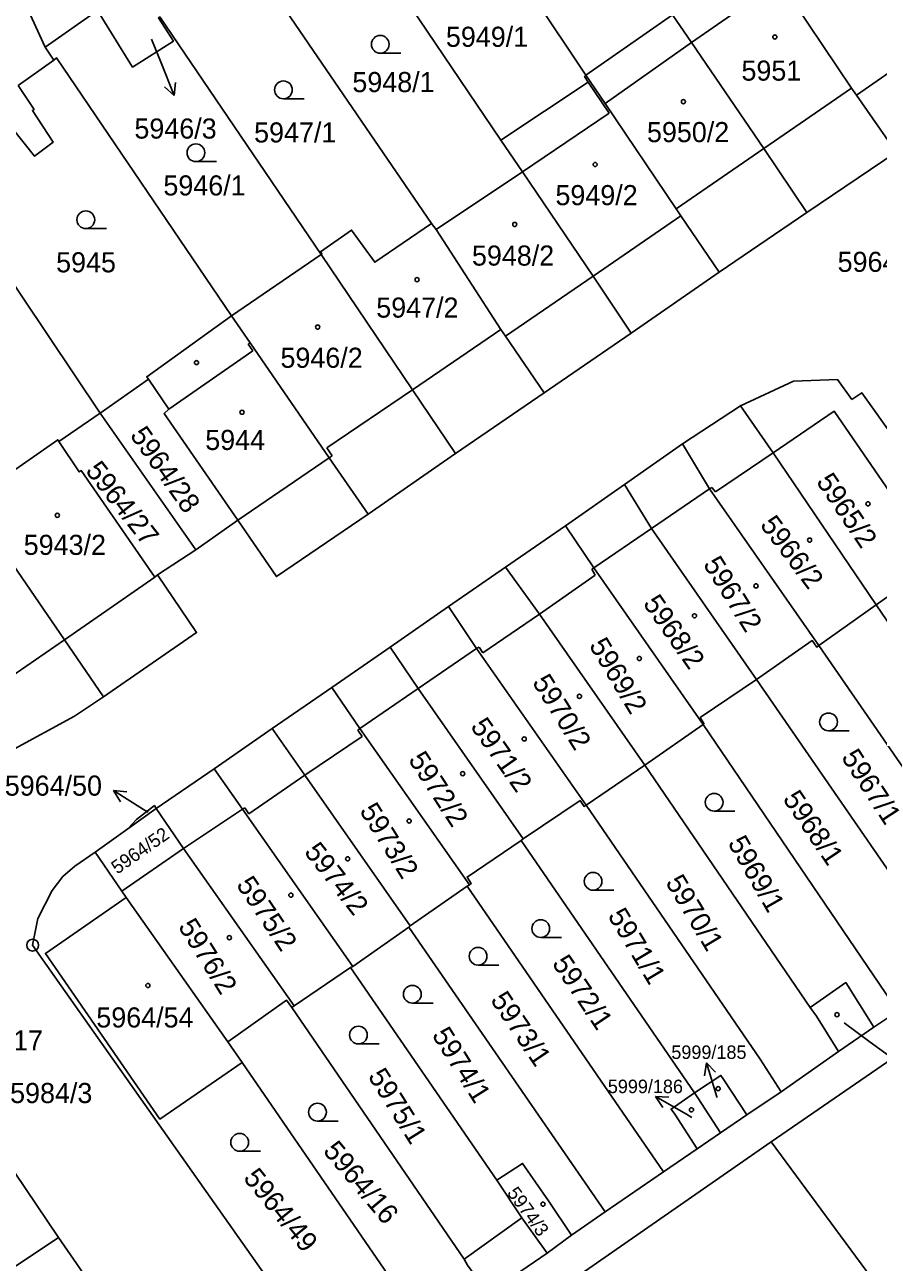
# Model space of a CAD drawing. Extents: x -644096 to -634268, y -1141430 to -1133463.
# Drawn here: x -639573 to -639500.8, y -1138928.4 to -1138823.8 of the extents above; entities that cross this region are included whole.
import ezdxf

# ---------------------------------------------------------------- set-up
doc = ezdxf.new("R2010")
doc.units = 0
for name, color, linetype in [('_CIVIL_CONSTRUCTION', 7, 'Continuous'), ('M_Svah_Nasyp', 7, 'Continuous'), ('M_Svah_Zarez', 7, 'Continuous'), ('svrsek_osa_sjezdy', 7, 'Continuous'), ('svrsek_osa_terminal_VRT', 7, 'Continuous'), ('svrsek_osa_VRT', 7, 'Continuous'), ('svrsek_popisy_VRT', 7, 'Continuous'), ('terminal_VRT', 7, 'Continuous')]:
    doc.layers.add(name, color=color, linetype=linetype)

msp = doc.modelspace()

# ---------------------------------------------------------------- linework, layer by layer
at = {"layer": '_CIVIL_CONSTRUCTION'}
for radius in [0.5, 0.0303]:
    msp.add_circle((-639572.35, -1138901.62), radius, dxfattribs=at)
at = {"layer": 'M_Svah_Nasyp'}
for p, q in [((-639509.18, -1138820.11), (-639516.63, -1138825.29)), ((-639502.69, -1138829.74), (-639494.75, -1138824.25)), ((-639523.93, -1138830.46), (-639516.63, -1138825.29)), ((-639523.6, -1138831.28), (-639525.36, -1138828.65)), ((-639510.51, -1138834.25), (-639503.1, -1138829.15)), ((-639530.93, -1138836.23), (-639523.6, -1138831.28)), ((-639510.51, -1138834.25), (-639517.92, -1138839.35)), ((-639517.53, -1138839.95), (-639524.94, -1138845.06)), ((-639524.94, -1138845.06), (-639532.37, -1138850.13)), ((-639532.76, -1138849.56), (-639540.24, -1138854.66)), ((-639560.84, -1138856.3), (-639553.74, -1138851.38)), ((-639554.12, -1138850.8), (-639553.96, -1138850.69)), ((-639553.74, -1138851.38), (-639554.12, -1138850.8)), ((-639547.46, -1138859.58), (-639540.24, -1138854.66)), ((-639547.01, -1138860.24), (-639547.46, -1138859.58)), ((-639547.26, -1138860.4), (-639555, -1138865.68)), ((-639547.26, -1138860.4), (-639547.01, -1138860.24)), ((-639509.74, -1138860), (-639514.6, -1138863.29)), ((-639514.92, -1138862.93), (-639515.11, -1138863.04)), ((-639514.6, -1138863.29), (-639514.92, -1138862.93)), ((-639520.02, -1138866.39), (-639515.11, -1138863.04)), ((-639524.89, -1138869.71), (-639520.02, -1138866.39)), ((-639525.06, -1138869.83), (-639524.89, -1138869.71)), ((-639524.78, -1138870.34), (-639525.06, -1138869.83)), ((-639569.66, -1138875.81), (-639562, -1138870.51)), ((-639529.49, -1138873.64), (-639524.78, -1138870.34)), ((-639534.28, -1138876.91), (-639529.49, -1138873.64)), ((-639577.07, -1138880.92), (-639569.66, -1138875.81)), ((-639539.74, -1138879.92), (-639534.81, -1138876.54)), ((-639534.81, -1138876.54), (-639534.6, -1138876.43)), ((-639534.28, -1138876.91), (-639534.6, -1138876.43)), ((-639544.68, -1138883.31), (-639539.74, -1138879.92)), ((-639544.85, -1138883.43), (-639544.68, -1138883.31)), ((-639544.49, -1138883.98), (-639544.85, -1138883.43)), ((-639549.32, -1138887.25), (-639544.49, -1138883.98)), ((-639554.06, -1138890.52), (-639549.32, -1138887.25)), ((-639559.58, -1138893.45), (-639554.59, -1138890.13)), ((-639554.59, -1138890.13), (-639554.4, -1138890.01)), ((-639554.4, -1138890.01), (-639554.06, -1138890.52))]:
    msp.add_line(p, q, dxfattribs=at)
at = {"layer": 'M_Svah_Zarez'}
for centre in [(-639509.59, -1138824.83), (-639517.32, -1138830.3), (-639524.78, -1138835.61), (-639531.58, -1138840.68), (-639539.84, -1138845.35), (-639548.24, -1138849.36), (-639558.49, -1138852.36), (-639554.64, -1138856.56), (-639501.71, -1138864.3), (-639570.26, -1138865.27), (-639506.65, -1138867.37), (-639511.18, -1138871.24), (-639516.38, -1138873.77), (-639521.05, -1138877.38), (-639526.11, -1138880.58), (-639530.78, -1138884.18), (-639535.98, -1138887.12), (-639540.51, -1138891.12), (-639545.71, -1138894.32), (-639550.51, -1138897.39), (-639555.71, -1138900.99), (-639562.6, -1138905.03), (-639504.33, -1138907.49), (-639514.38, -1138913.75), (-639516.64, -1138915.54), (-639529.19, -1138923.52)]:
    msp.add_circle(centre, 0.175, dxfattribs=at)
at = {"layer": 'svrsek_osa_sjezdy'}
for p, q in [((-639542.95, -1138826.2), (-639541.2, -1138826.2)), ((-639551.14, -1138830.05), (-639549.39, -1138830.05)), ((-639558.54, -1138835.37), (-639556.79, -1138835.37)), ((-639567.85, -1138841.03), (-639566.1, -1138841.03)), ((-639505.05, -1138883.49), (-639503.3, -1138883.49)), ((-639514.72, -1138890.29), (-639512.97, -1138890.29)), ((-639524.96, -1138896.97), (-639523.21, -1138896.97)), ((-639529.38, -1138900.97), (-639527.63, -1138900.97)), ((-639534.68, -1138903.31), (-639532.93, -1138903.31)), ((-639540.24, -1138906.52), (-639538.49, -1138906.52)), ((-639544.8, -1138909.97), (-639543.05, -1138909.97)), ((-639548.26, -1138916.49), (-639546.51, -1138916.49)), ((-639554.84, -1138919.04), (-639553.09, -1138919.04))]:
    msp.add_line(p, q, dxfattribs=at)
for centre in [(-639542.95, -1138825.45), (-639551.14, -1138829.3), (-639558.54, -1138834.62), (-639567.85, -1138840.28), (-639505.05, -1138882.74), (-639514.72, -1138889.54), (-639524.96, -1138896.22), (-639529.38, -1138900.22), (-639534.68, -1138902.56), (-639540.24, -1138905.77), (-639544.8, -1138909.22), (-639548.26, -1138915.74), (-639554.84, -1138918.29)]:
    msp.add_circle(centre, 0.75, dxfattribs=at)
at = {"layer": 'svrsek_osa_terminal_VRT'}
msp.add_arc((-642050.26, -1145189.6), 8802.25, 41.413152, 75.317049, dxfattribs=at)
at = {"layer": 'svrsek_popisy_VRT'}
for p, q in [((-639562.29, -1138825), (-639561.49, -1138827.01)), ((-639561.49, -1138827.01), (-639560.37, -1138829.79)), ((-639560.37, -1138829.79), (-639561.2, -1138829.05)), ((-639560.37, -1138829.79), (-639560.28, -1138828.68)), ((-639562.96, -1138890.14), (-639565.51, -1138888.55)), ((-639565.51, -1138888.55), (-639564.39, -1138888.66)), ((-639565.51, -1138888.55), (-639564.92, -1138889.51)), ((-639562.59, -1138890.37), (-639562.96, -1138890.14)), ((-639503.72, -1138908.2), (-639501.52, -1138909.83)), ((-639501.52, -1138909.83), (-639499.09, -1138911.59)), ((-639515.37, -1138911.56), (-639515.55, -1138912.66)), ((-639514.49, -1138914.43), (-639515.37, -1138911.56)), ((-639515.37, -1138911.56), (-639514.6, -1138912.37)), ((-639517.07, -1138915.91), (-639519.67, -1138914.41)), ((-639519.67, -1138914.41), (-639518.55, -1138914.48)), ((-639519.67, -1138914.41), (-639519.05, -1138915.34)), ((-639514.47, -1138914.5), (-639514.49, -1138914.43)), ((-639516.6, -1138916.18), (-639517.07, -1138915.91))]:
    msp.add_line(p, q, dxfattribs=at)
at = {"layer": 'terminal_VRT'}
for p, q in [((-639525.56, -1138828.06), (-639537.65, -1138809.99)), ((-639571.3, -1138825.68), (-639566.85, -1138822.59)), ((-639547.95, -1138843.22), (-639561.6, -1138823.13)), ((-639525.56, -1138828.06), (-639518.25, -1138822.95)), ((-639571.3, -1138825.68), (-639570.56, -1138826.78)), ((-639570.56, -1138826.78), (-639573.56, -1138828.94)), ((-639530.93, -1138836.23), (-639532.76, -1138833.54)), ((-639499.34, -1138834.57), (-639506.87, -1138839.66)), ((-639566.64, -1138856.63), (-639581.25, -1138834.83)), ((-639538.23, -1138841.11), (-639530.93, -1138836.23)), ((-639506.87, -1138839.66), (-639514.3, -1138844.71)), ((-639538.23, -1138841.11), (-639538.61, -1138840.6)), ((-639555.54, -1138848.4), (-639547.95, -1138843.22)), ((-639514.3, -1138844.71), (-639521.73, -1138849.88)), ((-639521.73, -1138849.88), (-639529.09, -1138854.92)), ((-639566.64, -1138856.63), (-639562.56, -1138853.76)), ((-639529.09, -1138854.92), (-639536.58, -1138860.04)), ((-639570.12, -1138859.02), (-639566.64, -1138856.63)), ((-639558.56, -1138868.18), (-639566.64, -1138856.63)), ((-639517.41, -1138859.23), (-639512.49, -1138856.01)), ((-639512.49, -1138856.01), (-639509.74, -1138860)), ((-639522.31, -1138862.66), (-639517.41, -1138859.23)), ((-639536.58, -1138860.04), (-639543.98, -1138865.18)), ((-639509.74, -1138860), (-639501.02, -1138872.85)), ((-639527.3, -1138866.16), (-639522.31, -1138862.66)), ((-639555, -1138865.68), (-639558.56, -1138868.18)), ((-639532.36, -1138869.65), (-639527.3, -1138866.16)), ((-639558.56, -1138868.18), (-639561.78, -1138870.32)), ((-639537.17, -1138872.97), (-639532.36, -1138869.65)), ((-639542.11, -1138876.41), (-639537.17, -1138872.97)), ((-639501.02, -1138872.85), (-639505.86, -1138876.28)), ((-639547.06, -1138879.82), (-639542.11, -1138876.41)), ((-639505.86, -1138876.28), (-639491.18, -1138897.63)), ((-639511.15, -1138879.15), (-639494.22, -1138903.71)), ((-639552.08, -1138883.29), (-639547.06, -1138879.82)), ((-639557, -1138886.71), (-639552.08, -1138883.29)), ((-639515.66, -1138882.95), (-639520.59, -1138886.41)), ((-639515.66, -1138882.95), (-639499.19, -1138907.2)), ((-639561.89, -1138890.06), (-639557, -1138886.71)), ((-639520.59, -1138886.41), (-639525.55, -1138889.77)), ((-639520.59, -1138886.41), (-639506.59, -1138906.88)), ((-639564.3, -1138891.77), (-639561.89, -1138890.06)), ((-639561.89, -1138890.06), (-639559.58, -1138893.45)), ((-639567.07, -1138893.75), (-639564.3, -1138891.77)), ((-639530.87, -1138892.64), (-639531.03, -1138892.78)), ((-639531.03, -1138892.78), (-639516.37, -1138914.11)), ((-639564.8, -1138897.06), (-639567.07, -1138893.75)), ((-639559.58, -1138893.45), (-639564.8, -1138897.06)), ((-639559.58, -1138893.45), (-639550.23, -1138906.76)), ((-639564.8, -1138897.06), (-639564.43, -1138897.58)), ((-639535.59, -1138896.63), (-639540.41, -1138899.99)), ((-639535.42, -1138896.51), (-639535.59, -1138896.63)), ((-639535.59, -1138896.63), (-639519, -1138920.79)), ((-639564.43, -1138897.58), (-639555.85, -1138909.78)), ((-639540.55, -1138900.09), (-639545.27, -1138903.41)), ((-639540.41, -1138899.99), (-639540.55, -1138900.09)), ((-639540.55, -1138900.09), (-639523.94, -1138924.18)), ((-639545.48, -1138903.51), (-639550.23, -1138906.76)), ((-639545.27, -1138903.41), (-639545.48, -1138903.51)), ((-639545.48, -1138903.51), (-639533.09, -1138921.5)), ((-639550.23, -1138906.76), (-639550.44, -1138906.9)), ((-639535.87, -1138928.18), (-639550.44, -1138906.9)), ((-639501.23, -1138908.55), (-639499.19, -1138907.2)), ((-639501.23, -1138908.55), (-639504.21, -1138910.62)), ((-639555.85, -1138909.78), (-639554.64, -1138911.54)), ((-639509.06, -1138914.01), (-639504.21, -1138910.62)), ((-639554.64, -1138911.54), (-639540.51, -1138932.07)), ((-639511.97, -1138915.97), (-639509.06, -1138914.01)), ((-639511.97, -1138915.97), (-639514.17, -1138917.49)), ((-639540.73, -1138939.64), (-639509.89, -1138918.26)), ((-639514.17, -1138917.49), (-639516.17, -1138918.83)), ((-639499.3, -1138932.58), (-639509.89, -1138918.26)), ((-639519, -1138920.79), (-639516.17, -1138918.83)), ((-639573.89, -1138920.81), (-639570.15, -1138926.35)), ((-639530.97, -1138924.68), (-639533.09, -1138921.5)), ((-639523.94, -1138924.18), (-639519, -1138920.79)), ((-639535.87, -1138928.18), (-639530.97, -1138924.68)), ((-639530.97, -1138924.68), (-639528.85, -1138927.65)), ((-639526.78, -1138926.13), (-639523.94, -1138924.18)), ((-639570.15, -1138926.35), (-639566.41, -1138931.73)), ((-639526.78, -1138926.13), (-639528.85, -1138927.65)), ((-639535.58, -1138928.68), (-639535.87, -1138928.18))]:
    msp.add_line(p, q, dxfattribs=at)
for points in [[(-639615.92, -1138753.63), (-639591.98, -1138749.98), (-639575.02, -1138799.47), (-639577.91, -1138811.29), (-639571.3, -1138825.68)], [(-639532.76, -1138833.54), (-639543.8, -1138817.19), (-639545.2, -1138815.19)], [(-639499.34, -1138834.57), (-639502.69, -1138829.74), (-639503.1, -1138829.15), (-639509.18, -1138820.11), (-639510.81, -1138817.72)], [(-639538.61, -1138840.6), (-639551.25, -1138822.13), (-639552.51, -1138820.23)], [(-639561.6, -1138823.13), (-639561.71, -1138823.22), (-639560.44, -1138825.18), (-639563.9, -1138827.37), (-639566.85, -1138822.59)], [(-639506.87, -1138839.66), (-639510.51, -1138834.25), (-639516.63, -1138825.29), (-639518.25, -1138822.95)], [(-639555.54, -1138848.4), (-639570.32, -1138826.6), (-639570.56, -1138826.78)], [(-639532.76, -1138833.54), (-639525.36, -1138828.65), (-639525.67, -1138828.16), (-639525.56, -1138828.06)], [(-639514.3, -1138844.71), (-639517.53, -1138839.95), (-639517.92, -1138839.35), (-639523.93, -1138830.46), (-639525.56, -1138828.06)], [(-639573.56, -1138828.94), (-639572.23, -1138830.96), (-639572.36, -1138831.05), (-639570.61, -1138833.71), (-639572.18, -1138834.92), (-639574.04, -1138832.56), (-639577.85, -1138835.44), (-639579.13, -1138833.21)], [(-639521.73, -1138849.88), (-639524.94, -1138845.06), (-639530.93, -1138836.23)], [(-639547.95, -1138843.22), (-639547.88, -1138843.17), (-639548, -1138842.99), (-639545.38, -1138841.16), (-639543.42, -1138843.88), (-639538.61, -1138840.6)], [(-639529.09, -1138854.92), (-639532.37, -1138850.13), (-639532.76, -1138849.56), (-639538.23, -1138841.11)], [(-639536.58, -1138860.04), (-639540.24, -1138854.66), (-639547.95, -1138843.22)], [(-639555.54, -1138848.4), (-639562.7, -1138853.56), (-639562.56, -1138853.76)], [(-639543.98, -1138865.18), (-639547.26, -1138860.4), (-639553.96, -1138850.69), (-639555.54, -1138848.4)], [(-639562.56, -1138853.76), (-639560.84, -1138856.3), (-639561.23, -1138856.67), (-639555, -1138865.68)], [(-639512.49, -1138856.01), (-639508.01, -1138853.94), (-639504.28, -1138853.8), (-639503.09, -1138855.47)], [(-639503.09, -1138855.47), (-639502.24, -1138854.91), (-639481.98, -1138883.33)], [(-639509.74, -1138860), (-639504.57, -1138856.48), (-639495.83, -1138869.18), (-639501.02, -1138872.85)], [(-639577.7, -1138864.1), (-639570.22, -1138858.89), (-639570.12, -1138859.02)], [(-639561.78, -1138870.32), (-639562, -1138870.51), (-639568.24, -1138861.49), (-639568.4, -1138861.6), (-639570.12, -1138859.02)], [(-639517.41, -1138859.23), (-639515.11, -1138863.04), (-639505.86, -1138876.28)], [(-639522.31, -1138862.66), (-639520.02, -1138866.39), (-639511.15, -1138879.15)], [(-639543.98, -1138865.18), (-639551.73, -1138870.46), (-639555, -1138865.68)], [(-639566.35, -1138880.62), (-639569.66, -1138875.81), (-639575.81, -1138866.86)], [(-639527.3, -1138866.16), (-639524.89, -1138869.71), (-639515.66, -1138882.95)], [(-639532.36, -1138869.65), (-639529.49, -1138873.64), (-639520.59, -1138886.41)], [(-639561.78, -1138870.32), (-639558.49, -1138875.19), (-639566.35, -1138880.62)], [(-639537.17, -1138872.97), (-639534.81, -1138876.54), (-639525.55, -1138889.77)], [(-639501.02, -1138872.85), (-639491.18, -1138887.26), (-639491.04, -1138887.18), (-639488.75, -1138890.53), (-639488.1, -1138891.47)], [(-639542.11, -1138876.41), (-639539.74, -1138879.92), (-639530.87, -1138892.64)], [(-639505.86, -1138876.28), (-639506.04, -1138876.41), (-639506.42, -1138875.86), (-639511.15, -1138879.15)], [(-639511.15, -1138879.15), (-639515.89, -1138882.38), (-639515.59, -1138882.89), (-639515.66, -1138882.95)], [(-639566.35, -1138880.62), (-639568.81, -1138882.26), (-639574.19, -1138885.2)], [(-639547.06, -1138879.82), (-639544.68, -1138883.31), (-639535.42, -1138896.51)], [(-639552.08, -1138883.29), (-639549.32, -1138887.25), (-639540.41, -1138899.99)], [(-639557, -1138886.71), (-639554.59, -1138890.13), (-639545.27, -1138903.41)], [(-639564.3, -1138891.77), (-639563.56, -1138890.99), (-639562.05, -1138889.82), (-639561.89, -1138890.06)], [(-639525.55, -1138889.77), (-639525.72, -1138889.89), (-639526.06, -1138889.4), (-639530.87, -1138892.64)], [(-639525.55, -1138889.77), (-639510.82, -1138911.26), (-639509.06, -1138914.01)], [(-639531.03, -1138892.78), (-639535.61, -1138895.86), (-639535.26, -1138896.4), (-639535.42, -1138896.51)], [(-639509.89, -1138918.26), (-639485.89, -1138901.74), (-639473.65, -1138893.11)], [(-639546.64, -1138936.29), (-639547.51, -1138936.89), (-639572.35, -1138901.62), (-639571.9, -1138899.36), (-639570.69, -1138897), (-639569.78, -1138895.8), (-639568.78, -1138894.95), (-639567.07, -1138893.75)], [(-639554.64, -1138911.54), (-639561.58, -1138916.33), (-639571.27, -1138902.31), (-639564.43, -1138897.58)], [(-639506.59, -1138906.88), (-639503.59, -1138904.79), (-639501.23, -1138908.55)], [(-639550.44, -1138906.9), (-639550.87, -1138906.27), (-639555.85, -1138909.78)], [(-639504.21, -1138910.62), (-639506.07, -1138907.63), (-639506.59, -1138906.88)], [(-639516.37, -1138914.11), (-639514.15, -1138912.63), (-639513.9, -1138913), (-639511.97, -1138915.97)], [(-639516.17, -1138918.83), (-639518.05, -1138915.91), (-639518.36, -1138915.48), (-639516.37, -1138914.11)], [(-639516.37, -1138914.11), (-639516.09, -1138914.54), (-639514.17, -1138917.49)], [(-639533.09, -1138921.5), (-639530.92, -1138920.07), (-639528.73, -1138923.23), (-639526.78, -1138926.13)], [(-639570.15, -1138926.35), (-639573.92, -1138928.85), (-639586.33, -1138937.4), (-639587.13, -1138937.92), (-639587.79, -1138938.35)], [(-639528.85, -1138927.65), (-639533.82, -1138931.08), (-639535.58, -1138928.68)]]:
    msp.add_lwpolyline(points, dxfattribs=at)

# ---------------------------------------------------------------- texts
at = {"layer": 'svrsek_osa_VRT'}
for s, height, p in [('5949/1', 1.7, (-639537.4, -1138825.66)), ('5951', 1.7, (-639512.41, -1138828.52)), ('5948/1', 1.7, (-639545.31, -1138829.49)), ('5946/3', 1.7, (-639563.74, -1138833.42)), ('5947/1', 1.7, (-639553.62, -1138833.75)), ('5950/2', 1.7, (-639520.4, -1138833.72)), ('5946/1', 1.7, (-639561.29, -1138838.23)), ('5949/2', 1.7, (-639528.14, -1138839.05)), ('5945', 1.7, (-639570.36, -1138844.73)), ('5948/2', 1.7, (-639535.2, -1138844.16)), ('5964/45', 1.7, (-639504.28, -1138844.69)), ('5947/2', 1.7, (-639543.29, -1138848.56)), ('5946/2', 1.7, (-639551.39, -1138852.8)), ('5944', 1.7, (-639557.75, -1138859.75)), ('5943/2', 1.7, (-639573.1, -1138868.62)), ('5964/50', 1.7, (-639574.7, -1138888.98)), ('5964/54', 1.7, (-639566.96, -1138908.58)), ('5998/17', 1.7, (-639579.69, -1138910.52)), ('5999/185', 1.139, (-639518.34, -1138911.24)), ('5999/186', 1.139, (-639523.71, -1138914.13)), ('5984/3', 1.7, (-639574.25, -1138914.97))]:
    msp.add_text(s, height=height, dxfattribs=at).set_placement(p)
for s, height, rotation, p in [('5964/28', 1.7, 305, (-639564.17, -1138858.51)), ('5964/27', 1.7, 308, (-639567.94, -1138861.53)), ('5965/2', 1.7, 304, (-639506.14, -1138862.43)), ('5966/2', 1.7, 307, (-639510.9, -1138866.1)), ('5967/2', 1.7, 302, (-639515.7, -1138869.41)), ('5968/2', 1.7, 305, (-639520.79, -1138872.74)), ('5969/2', 1.7, 301, (-639525.34, -1138876.27)), ('5970/2', 1.7, 302, (-639530.15, -1138879.39)), ('5971/2', 1.7, 305, (-639535.38, -1138883.14)), ('5972/2', 1.7, 303, (-639540.63, -1138885.94)), ('5967/1', 1.7, 303, (-639504.02, -1138885.74)), ('5968/1', 1.7, 304, (-639508.97, -1138889.26)), ('5973/2', 1.7, 302, (-639544.75, -1138890.26)), ('5964/52', 1.139, 35, (-639565.19, -1138895.66)), ('5974/2', 1.7, 308, (-639549.45, -1138893.76)), ('5969/1', 1.7, 300, (-639513.61, -1138892.98)), ('5975/2', 1.7, 304, (-639555.18, -1138896.52)), ('5970/1', 1.7, 301, (-639518.88, -1138896.31)), ('5971/1', 1.7, 301, (-639523.76, -1138899.13)), ('5976/2', 1.7, 302, (-639560.09, -1138900.04)), ('5972/1', 1.7, 304, (-639528.48, -1138903.17)), ('5973/1', 1.7, 304, (-639533.69, -1138906.26)), ('5974/1', 1.7, 302, (-639538.63, -1138909.22)), ('5975/1', 1.7, 302, (-639544.04, -1138912.7)), ('5964/16', 1.7, 310, (-639547.86, -1138919.06)), ('5964/49', 1.7, 309, (-639554.6, -1138921.34)), ('5974/3', 1.139, 306, (-639532.28, -1138922.58))]:
    msp.add_text(s, height=height, rotation=rotation, dxfattribs=at).set_placement(p)

doc.saveas('drawing.dxf')
